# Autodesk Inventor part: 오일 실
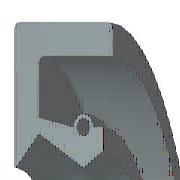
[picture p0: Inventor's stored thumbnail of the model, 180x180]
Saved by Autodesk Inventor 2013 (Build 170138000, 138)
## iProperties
Created: 2015-11
Part Number: 오일 실
Material: 고무
Description: 오일-실
Document SubType Name: Modeling
Standard: KS B 2804
Designer: mdu
Standards Organization: KS
Language: ko-KR
Size Designation: D - 10 20 7
Categories: <MemberInstance><Categories><Category DisplayName="샤프트 부품" InternalName="7f7aeb1f-a693-4053-b835-cee3144e0d98" Mnemonic="SHFT"><Category DisplayName="실링" Intern
Density: 0.93 g/cm^3
Mass: 1.11329 g
Surface Area: 16.3871 cm^2
Volume: 1.19708 cm^3
IsCustomPart: 0
Author: mdu
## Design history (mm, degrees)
revolve "본체" stored, may be unused: angle "d17" = 90 deg
revolve "스프링1" stored, may be unused: angle "d18" = 90 deg
body "Solid1"
sketch "스케치1"
  geometry: L1 (0, 10)-(7, 10); L2 (7, 8.25)-(1.75, 8.25); L3 (1.75, 6.75)-(4.9, 5); L4 (4.9, 5)-(0, 5); L5 (0, 0)-(9.586, 0) reference; L6 (4.9, 5)-(6.3, 5.875); L7 (0, 18)-(0, -3) reference; L8 (-1.941, 0)-(11.507, 0) reference; L9 (4.2, 7.1)-(1.75, 7.59); L10 (1.75, 7.59)-(1.75, 8.25); L11 (0, 10)-(0, 5.088); L12 (4.9, 5)-(0, 5); L13 (1.75, 6.75)-(0.152, 5.028); L14 (7, 10)-(7, 8.25); L15 (5.6, 7.1)-(6.3, 7.1); L16 (6.3, 7.1)-(6.3, 5.875); C1 r 0.455 at (4.9, 7.1); A1 r 0.7 centre (4.9, 7.1) between (5.6, 7.1) and (4.2, 7.1); A2 r 0.088 centre (0.088, 5.088) between (0, 5.088) and (0.152, 5.028); 1 further point
  constraints: 28 end point, 5 horizontal alignment, 5 point on line, 4 point on circle, 4 vertical alignment, 3 centre point, 3 tangent, 2 collinear, 2 horizontal, 2 perpendicular, 1 coincident, 1 parallel
  dimensions: "d0" = 20 diameter of L1 L5 (= SD2); "d1" = 1.75 distance of L1.end L2.start (= SD); "d2" = 0.91 diameter of C1 (= SPDI); "d3" = 1.4 diameter of A1 (= SPDA); "d4" = 10 diameter of L3.end L5 (= NND); "d5" = 13.5 diameter of L3.start L5 (= TKDM); "d7" = 15.18 diameter of L9.end L5 (= TKDM + 0.24 x SWDT); "d8" = 1.75 distance between parallel lines of L11 L10 (= SD); "d9" = 4.9 distance from line of L11 C1.centre (= SPDST); "d10" = 14.2 diameter of C1.centre L5 (= HLDM); "d11" = 0.0875 radius of A2 (= 0.25 x LAB); "d12" = 6.3 distance between parallel lines of L11 L16 (= SDI); "d13" = 11.75 diameter of L6.end L5 (= ABDM); "d14" = 7 distance from line of L11 L1.end (= SWDT)
fillet "모깎기1" dims "d6" = 0.3 (= RR)
other parameters: "SD2" = 20 [user parameter; used in 1 equation term], "SWDT" = 7 [user parameter; used in 2 equation terms], "RR" = 0.3 [user parameter; used in 1 equation term], "SD" = 1.75 [user parameter; used in 2 equation terms], "NND" = 10 [user parameter; used in 1 equation term], "SPDA" = 1.4 [user parameter; used in 1 equation term], "SPDI" = 0.91 [user parameter; used in 1 equation term], "TKDM" = 13.5 [user parameter; used in 2 equation terms], "HLDM" = 14.2 [user parameter; used in 1 equation term], "ABDM" = 11.75 [user parameter; used in 1 equation term], "SDI" = 6.3 [user parameter; used in 1 equation term], "SPDST" = 4.9 [user parameter; used in 1 equation term], "LAB" = 0.35 [user parameter; used in 1 equation term], "d15" = 0, "d16" = 0, "d19" = 0
